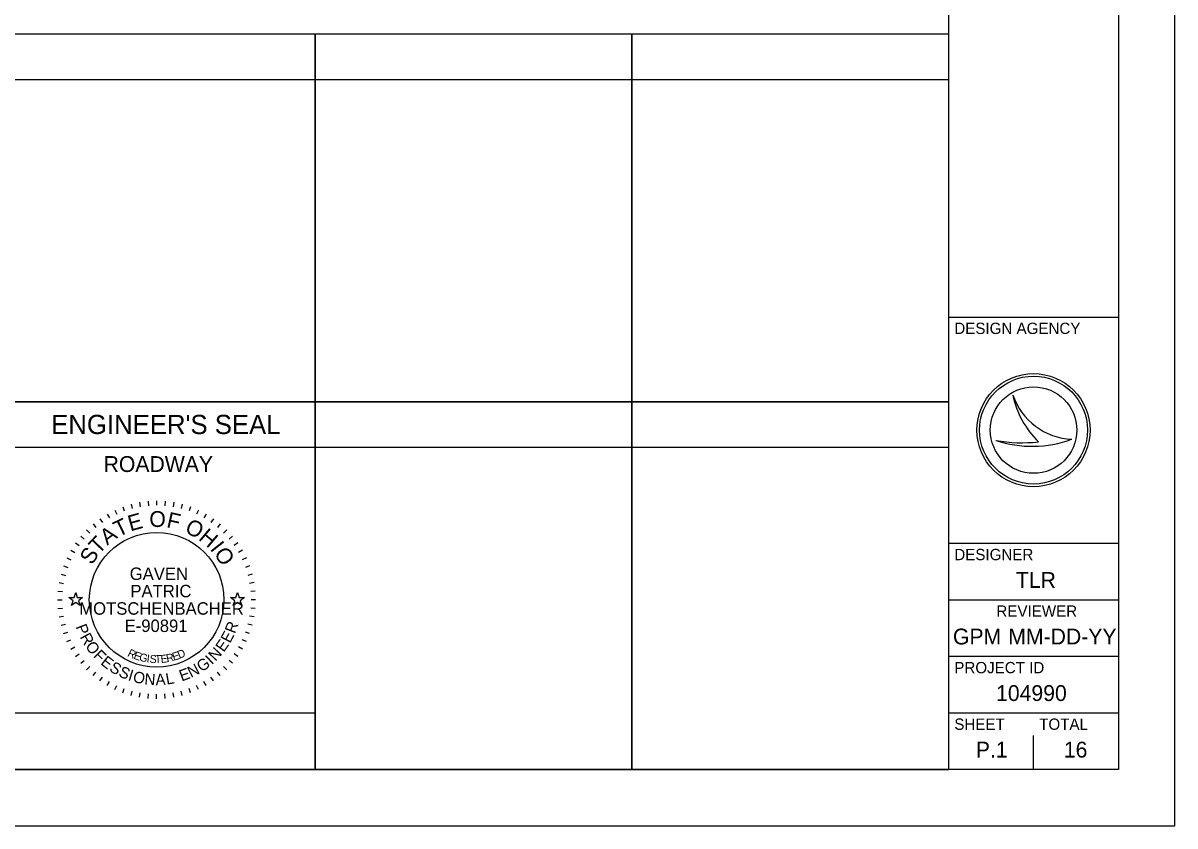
# Model space of a CAD drawing. Extents: x 0 to 34, y 0 to 22.
# Drawn here: x 23.82 to 34, y 0 to 7.1 of the extents above; entities that cross this region are included whole.
import ezdxf

# ---------------------------------------------------------------- set-up
doc = ezdxf.new("R2010")
doc.units = 0
for name, color, linetype in [('SH_Border', 7, 'Continuous'), ('SH_Cut_Line', 7, 'Continuous'), ('SH_Data', 7, 'Continuous'), ('SH_Seal', 7, 'Continuous')]:
    doc.layers.add(name, color=color, linetype=linetype)

msp = doc.modelspace()

# ---------------------------------------------------------------- linework, layer by layer
at = {"layer": 'SH_Border'}
for p, q in [((32, 0.5), (32, 21.5)), ((32, 4.5), (33.5, 4.5)), ((32, 2.5), (33.5, 2.5)), ((32, 2), (33.5, 2)), ((32, 1.5), (33.5, 1.5)), ((32, 1), (33.5, 1))]:
    msp.add_line(p, q, dxfattribs=at)
msp.add_lwpolyline([(1.5, 21.5), (33.5, 21.5), (33.5, 0.5), (1.5, 0.5)], close=True, dxfattribs=at)
at = {"layer": 'SH_Cut_Line'}
msp.add_lwpolyline([(0, 0), (34, 0), (34, 22), (0, 22)], close=True, dxfattribs=at)
at = {"layer": 'SH_Data'}
for p, q in [((23.6, 6.6), (26.4, 6.6)), ((26.4, 6.6), (29.2, 6.6)), ((29.2, 6.6), (32, 6.6)), ((32.567, 3.81), (32.567, 3.81)), ((23.6, 3.75), (26.4, 3.75)), ((26.4, 3.75), (26.4, 0.5)), ((32.75, 3.5), (32.75, 3.5)), ((32.417, 3.41), (32.417, 3.41)), ((33.087, 3.419), (33.087, 3.419)), ((23.6, 3.35), (26.4, 3.35)), ((23.6, 3.35), (26.4, 3.35)), ((26.4, 3.35), (29.2, 3.35)), ((29.2, 3.35), (32, 3.35)), ((32.75, 0.5), (32.75, 0.8)), ((32.375, 0.675), (32.375, 0.675)), ((23.6, 0.5), (26.4, 0.5))]:
    msp.add_line(p, q, dxfattribs=at)
for points in [[(26.4, 7), (23.6, 7), (23.6, 3.75), (26.4, 3.75)], [(29.2, 7), (26.4, 7), (26.4, 3.75), (29.2, 3.75)], [(32, 7), (29.2, 7), (29.2, 3.75), (32, 3.75)], [(26.4, 3.75), (23.6, 3.75), (23.6, 0.5), (26.4, 0.5)], [(29.2, 3.75), (26.4, 3.75), (26.4, 0.5), (29.2, 0.5)], [(32, 3.75), (29.2, 3.75), (29.2, 0.5), (32, 0.5)], [(23.6, 0.5), (23.6, 1), (26.4, 1), (26.4, 0.5)]]:
    msp.add_lwpolyline(points, close=True, dxfattribs=at)
for radius in [0.5, 0.477, 0.477, 0.382]:
    msp.add_circle((32.75, 3.5), radius, dxfattribs=at)
for centre, radius, start, end in [((33.116, 3.998), 0.58, 198.9257, 198.9319), ((33.347, 3.97), 0.796, 191.6379, 191.6421), ((33.116, 3.998), 0.58, 198.9319, 267.1657), ((33.347, 3.97), 0.796, 191.6421, 226.0947), ((32.739, 4.37), 1.013, 251.4576, 290.0832), ((32.648, 4.654), 1.266, 259.4964, 259.4995), ((32.739, 4.37), 1.013, 251.4527, 251.4576), ((32.648, 4.654), 1.266, 259.4995, 276.6672)]:
    msp.add_arc(centre, radius, start, end, dxfattribs=at)
at = {"layer": 'SH_Seal'}
for p, q in [((24.848, 2.862), (24.855, 2.822)), ((24.924, 2.872), (24.927, 2.832)), ((25, 2.875), (25, 2.835)), ((25.076, 2.872), (25.073, 2.832)), ((25.152, 2.862), (25.145, 2.822)), ((24.563, 2.758), (24.583, 2.723)), ((24.63, 2.793), (24.647, 2.757)), ((24.701, 2.822), (24.714, 2.785)), ((24.774, 2.845), (24.784, 2.807)), ((25.226, 2.845), (25.216, 2.807)), ((25.299, 2.822), (25.286, 2.785)), ((25.37, 2.793), (25.353, 2.757)), ((25.437, 2.758), (25.417, 2.723)), ((24.438, 2.67), (24.463, 2.64)), ((24.498, 2.717), (24.521, 2.684)), ((25.502, 2.717), (25.479, 2.684)), ((25.562, 2.67), (25.537, 2.64)), ((24.33, 2.562), (24.36, 2.537)), ((24.381, 2.619), (24.41, 2.59)), ((25.619, 2.619), (25.59, 2.59)), ((25.67, 2.562), (25.64, 2.537)), ((24.283, 2.502), (24.316, 2.479)), ((25.717, 2.502), (25.684, 2.479)), ((24.207, 2.37), (24.243, 2.353)), ((24.242, 2.438), (24.277, 2.418)), ((25.758, 2.438), (25.723, 2.418)), ((25.793, 2.37), (25.757, 2.353)), ((24.178, 2.299), (24.215, 2.286)), ((25.822, 2.299), (25.785, 2.286)), ((24.138, 2.152), (24.178, 2.145)), ((24.155, 2.226), (24.193, 2.216)), ((25.845, 2.226), (25.807, 2.216)), ((25.862, 2.152), (25.822, 2.145)), ((24.128, 2.076), (24.168, 2.073)), ((25.872, 2.076), (25.832, 2.073)), ((24.125, 2), (24.165, 2)), ((25.875, 2), (25.835, 2)), ((24.128, 1.924), (24.168, 1.927)), ((24.138, 1.848), (24.178, 1.855)), ((25.862, 1.848), (25.822, 1.855)), ((25.872, 1.924), (25.832, 1.927)), ((24.155, 1.774), (24.193, 1.784)), ((25.845, 1.774), (25.807, 1.784)), ((24.178, 1.701), (24.215, 1.714)), ((24.207, 1.63), (24.243, 1.647)), ((25.793, 1.63), (25.757, 1.647)), ((25.822, 1.701), (25.785, 1.714)), ((24.242, 1.563), (24.277, 1.583)), ((25.758, 1.563), (25.723, 1.583)), ((24.283, 1.498), (24.316, 1.521)), ((24.33, 1.438), (24.36, 1.463)), ((25.67, 1.438), (25.64, 1.463)), ((25.717, 1.498), (25.684, 1.521)), ((24.381, 1.381), (24.41, 1.41)), ((24.438, 1.33), (24.463, 1.36)), ((25.562, 1.33), (25.537, 1.36)), ((25.619, 1.381), (25.59, 1.41)), ((24.498, 1.283), (24.521, 1.316)), ((24.563, 1.242), (24.583, 1.277)), ((24.63, 1.207), (24.647, 1.243)), ((25.37, 1.207), (25.353, 1.243)), ((25.437, 1.242), (25.417, 1.277)), ((25.502, 1.283), (25.479, 1.316)), ((24.701, 1.178), (24.714, 1.215)), ((24.774, 1.155), (24.784, 1.193)), ((24.848, 1.138), (24.855, 1.178)), ((24.924, 1.128), (24.927, 1.168)), ((25, 1.125), (25, 1.165)), ((25.076, 1.128), (25.073, 1.168)), ((25.152, 1.138), (25.145, 1.178)), ((25.226, 1.155), (25.216, 1.193)), ((25.299, 1.178), (25.286, 1.215))]:
    msp.add_line(p, q, dxfattribs=at)
for points in [[(24.224, 2.02), (24.271, 2.02), (24.285, 2.065), (24.299, 2.02), (24.346, 2.02), (24.308, 1.992), (24.323, 1.948), (24.285, 1.975), (24.247, 1.948), (24.262, 1.992)], [(25.654, 2.02), (25.701, 2.02), (25.715, 2.065), (25.729, 2.02), (25.776, 2.02), (25.738, 1.992), (25.753, 1.948), (25.715, 1.975), (25.677, 1.948), (25.692, 1.992)]]:
    msp.add_lwpolyline(points, close=True, dxfattribs=at)
msp.add_circle((25, 2), 0.595, dxfattribs=at)

# ---------------------------------------------------------------- texts
at = {"layer": 'SH_Data'}
for s, height, p in [('DESIGN AGENCY', 0.1, (32.05, 4.35)), ("ENGINEER'S SEAL", 0.17, (24.068, 3.465)), ('ROADWAY', 0.14, (24.531, 3.13)), ('DESIGNER', 0.1, (32.05, 2.35)), ('TLR', 0.14, (32.594, 2.105)), ('REVIEWER', 0.1, (32.422, 1.85)), ('GPM', 0.14, (32.038, 1.605)), ('MM-DD-YY', 0.14, (32.527, 1.605)), ('PROJECT ID', 0.1, (32.05, 1.35)), ('104990', 0.14, (32.419, 1.105)), ('SHEET', 0.1, (32.05, 0.85)), ('TOTAL', 0.1, (32.8, 0.85)), ('P.1', 0.14, (32.24, 0.605)), ('16', 0.14, (33.018, 0.605))]:
    msp.add_text(s, height=height, dxfattribs=at).set_placement(p)
at = {"layer": 'SH_Seal'}
for s, height, rotation, p in [('E', 0.14, 15.7571, (24.768, 2.604)), ('O', 0.14, 359.7812, (24.935, 2.644)), ('F', 0.14, 347.4362, (25.081, 2.642)), ('T', 0.14, 25.7167, (24.662, 2.552)), ('O', 0.14, 332.2586, (25.24, 2.602)), ('T', 0.14, 46.4344, (24.488, 2.396)), ('A', 0.14, 36.4747, (24.563, 2.478)), ('H', 0.14, 319.9136, (25.363, 2.536)), ('S', 0.14, 57.1924, (24.428, 2.301)), ('I', 0.14, 308.367, (25.466, 2.448)), ('O', 0.14, 303.1491, (25.502, 2.409)), ('P', 0.1, 291.494, (24.282, 1.762)), ('R', 0.1, 69.2322, (25.692, 1.695)), ('R', 0.1, 298.7311, (24.319, 1.672)), ('E', 0.1, 54.758, (25.593, 1.531)), ('E', 0.1, 61.9951, (25.648, 1.61)), ('O', 0.1, 306.4666, (24.365, 1.588)), ('F', 0.1, 314.7068, (24.434, 1.498)), ('R', 0.07, 334.487, (24.737, 1.505)), ('E', 0.07, 341.04, (24.791, 1.48)), ('E', 0.07, 17.6836, (25.15, 1.46)), ('D', 0.07, 23.3052, (25.201, 1.477)), ('N', 0.1, 47.0224, (25.52, 1.451)), ('E', 0.1, 321.4393, (24.498, 1.435)), ('S', 0.1, 328.6764, (24.574, 1.375)), ('G', 0.07, 347.4752, (24.841, 1.462)), ('I', 0.07, 353.7858, (24.909, 1.447)), ('S', 0.07, 356.8926, (24.936, 1.443)), ('T', 0.07, 3.0061, (24.986, 1.439)), ('E', 0.07, 6.0117, (25.039, 1.441)), ('R', 0.07, 11.9184, (25.092, 1.447)), ('N', 0.1, 27.3113, (25.304, 1.308)), ('G', 0.1, 35.0469, (25.398, 1.357)), ('I', 0.1, 43.287, (25.487, 1.421)), ('S', 0.1, 335.9134, (24.656, 1.327)), ('I', 0.1, 343.1505, (24.741, 1.29)), ('O', 0.1, 346.8859, (24.784, 1.275)), ('N', 0.1, 355.1261, (24.889, 1.252)), ('A', 0.1, 2.8617, (24.992, 1.244)), ('L', 0.1, 10.0987, (25.089, 1.249)), ('E', 0.1, 20.0742, (25.221, 1.277))]:
    msp.add_text(s, height=height, rotation=rotation, dxfattribs=at).set_placement(p)
for s, p in [('GAVEN', (24.762, 2.175)), ('PATRIC', (24.768, 2.022)), ('MOTSCHENBACHER', (24.316, 1.868)), ('E-90891', (24.717, 1.715))]:
    msp.add_text(s, height=0.11, dxfattribs=at).set_placement(p)

doc.saveas('drawing.dxf')
